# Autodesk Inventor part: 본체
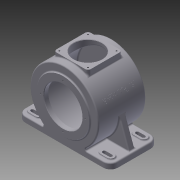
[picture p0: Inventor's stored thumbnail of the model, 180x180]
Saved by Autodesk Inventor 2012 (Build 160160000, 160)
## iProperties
Created: 2015-06
Part Number: 본체
Material: 알루미늄-6061
Document SubType Name: Modeling
Designer: Administrator
Density: 2.71 g/cm^3
Mass: 3341.53 g
Surface Area: 2292.88 cm^2
Volume: 1233.04 cm^3
Author: Administrator
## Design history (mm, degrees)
node "작업 평면2"
sketch "스케치9"
  geometry: L1 (-72, 0)-(62, 0); L2 (0, 0)-(0, 98.803); L3 (-72, 0)-(-72, 65); L4 (-72, 65)-(-59, 65); L5 (-59, 65)-(-59, 85); L6 (-59, 85)-(59, 85); L7 (59, 85)-(59, 65); L8 (59, 65)-(62, 65); L9 (62, 65)-(62, 0)
  constraints: 18 end point, 4 parallel, 4 perpendicular, 1 horizontal
  dimensions: "d23" = 72 distance from line of L2 L1.start; "d24" = 134 distance of L1.start L1.end; "d25" = 0 distance from line of L1 L2.start; "d26" = 13 distance of L3.end L4.end; "d27" = 118 distance of L5.end L6.end; "d28" = 130 diameter of L4 L1; "d29" = 170 diameter of L6 L1; "d30" = 130 diameter of L8 L1
revolve "회전2" sketch "스케치9" stored, may be unused: angle "d31" = 90 deg
sketch "스케치10"
  geometry: L1 (-115, 59)-(115, 59); L2 (115, 59)-(115, -59); L3 (115, -59)-(-115, -59); L4 (-115, -59)-(-115, 59); 2 further points
  constraints: 8 end point, 2 parallel, 1 horizontal, 1 midpoint, 1 perpendicular, 1 vertical alignment
  dimensions: "d32" = 118 distance of L3.end L1.start; "d34" = 230 distance of L1.start L1.end; "d37" = 59 distance from line of L3 point (0, 0)
extrude "돌출4" join sketch "스케치10" distance "d35" = 14; taper "d36" = 0 deg
sketch "스케치12"
  geometry: L1 (-115, -71)-(-46.733, -71) reference; L2 (46.733, -71)-(115, -71) reference; L3 (115, -85)-(115, -71) reference; L4 (-115, -85)-(115, -85) reference; L5 (-115, -85)-(-115, -71) reference; L6 (-115, -71)-(-46.733, -71) reference; L7 (-109, -71)-(-84.87, -4.703); C1 r 65 at (0, 0) reference; A1 r 85 centre (0, 0) between (46.733, -71) and (-46.733, -71) reference; A2 r 85 centre (0, 0) between (46.733, -71) and (-46.733, -71) reference; 1 further point
  constraints: 2 end point, 1 point on circle, 1 point on line
  dimensions: "d38" = 110 deg angle of L7 L1; "d39" = 6 distance from line of L7.start L5
extrude "돌출5" join sketch "스케치12" stored distance "d40" = 15; taper "d41" = 0 deg
node "작업 평면3"
sketch "스케치13"
  geometry: L1 (-42.5, 42.5)-(42.5, 42.5); L2 (42.5, 42.5)-(42.5, -42.5); L3 (42.5, -42.5)-(-42.5, -42.5); L4 (-42.5, -42.5)-(-42.5, 42.5); 3 further points
  constraints: 8 end point, 2 midpoint, 2 parallel, 1 horizontal, 1 horizontal alignment, 1 perpendicular, 1 vertical alignment
  dimensions: "d43" = 85 distance of L1.start L1.end; "d44" = 85 distance of L3.end L1.start
extrude "돌출6" join sketch "스케치13" stored distance "d45" = 15; taper "d46" = 0 deg
sketch "스케치14"
  geometry: L1 (-72, -65)-(-72, 65) reference; L2 (62, -65)-(62, 65) reference; L3 (-42.5, 88)-(42.5, 88) reference; L4 (-72, 0)-(62, 0); L5 (-64.5, 0)-(-64.5, 12); L6 (-61.5, 15)-(-61.5, 15); L7 (-61.5, 15)-(-61.5, 23.2); L8 (-61.2, 23.5)-(-48.5, 23.5); L9 (-47.5, 24.5)-(-47.5, 29.368); L10 (-47.5, 29.368)-(-49.268, 30.192); L11 (-51, 32.911)-(-51, 74); L12 (-48, 77)-(48, 77); L13 (51, 74)-(51, 47.5); L14 (51, 47.5)-(62, 47.5); L15 (-48.5, 23.5)-(-47.5, 24.5); L16 (59, -71)-(59, 85) reference; A1 r 0.3 centre (-61.2, 23.2) between (-61.2, 23.5) and (-61.5, 23.2); A2 r 3 centre (-61.5, 12) between (-61.5, 15) and (-64.5, 12); A3 r 3 centre (-48, 74) between (-48, 77) and (-51, 74); A4 r 3 centre (48, 74) between (51, 74) and (48, 77); A5 r 3 centre (-48, 32.911) between (-51, 32.911) and (-49.268, 30.192); 7 further points
  constraints: 24 end point, 14 point on line, 10 point on circle, 10 tangent, 6 parallel, 5 centre point, 3 perpendicular, 2 equal radius, 2 midpoint
  dimensions: "d47" = 154 diameter of L12 L4; "d48" = 102 distance of point (-51, 77) point (51, 77); "d50" = 95 diameter of L14 L4; "d51" = 115 deg angle of L11 L10; "d52" = 62 diameter of point (-51, 31) L4; "d53" = 14 distance of point (-61.5, 23.5) point (-47.5, 23.5); "d54" = 3 distance of point (-64.5, 15) L6.end; "d55" = 47 diameter of L8 L4; "d56" = 30 diameter of L6 L4; "d57" = 3.5 distance between parallel lines of L11 L9; "d58" = 0.3 radius of A1; "d59" = 3 radius of A2; "d60" = 1 distance of L8.end point (-47.5, 23.5); "d61" = 1 distance of L9.start point (-47.5, 23.5) (= d60); "d62" = 3 radius of A3; "d129" = 8 distance between parallel lines of L16 L13
revolve "회전3" sketch "스케치14" stored, may be unused: angle "d63" = 90 deg
chamfer "모따기1" distance "d64" = 1; stored, may be unused: second distance "d65" = 2, angle "d66" = 45 deg
sketch "스케치15"
  geometry: C1 r 35 at (0, 0); 1 further point
  constraints: 1 centre point, 1 coincident
  dimensions: "d67" = 70 diameter of C1
extrude "돌출7" cut sketch "스케치15" distance "d68" = 50; taper "d69" = 0 deg
fillet "모깎기1" dims "d70" = 3
chamfer "모따기2" distance "d71" = 1; stored, may be unused: second distance "d72" = 2, angle "d73" = 45 deg
sketch "스케치16"
  geometry: C1 r 36 at (0, 0) reference; 4 further points
  constraints: 2 horizontal alignment, 2 vertical alignment
  dimensions: "d74" = 71 distance of point (-35.5, -35.5) point (-35.5, 35.5); "d75" = 35.5 horizontal distance of C1.centre point (-35.5, 35.5); "d76" = 71 distance of point (35.5, 35.5) point (-35.5, 35.5) (= d74); "d77" = 35.5 horizontal distance of point (-35.5, 35.5) C1.centre (= d75)
hole "구멍1" sketch "스케치16" at (-35.5, 35.5), (-35.5, -35.5), (35.5, 35.5), (35.5, -35.5) diameter "d78" = 3.242; stored, may be unused: countersink angle "d82" = 90 deg, drill point angle "d84" = 118 deg; dims "d79" = 10, "d80" = 4, "d81" = 2, "d83" = 13
sketch "스케치17"
  geometry: L1 (115, -59)-(46.733, -59) reference; L2 (115, 59)-(115, -59) reference; L3 (97, -45)-(81, -45); L4 (97, -37)-(81, -37); A1 r 4 centre (97, -41) between (97, -45) and (97, -37); A2 r 4 centre (81, -41) between (81, -37) and (81, -45); 1 further point
  constraints: 4 end point, 4 point on circle, 4 tangent, 2 centre point, 1 horizontal alignment
  dimensions: "d85" = 8 diameter of A1; "d86" = 8 diameter of A2; "d87" = 16 distance of A2.centre A1.centre; "d88" = 18 distance from line of A1.centre L2; "d89" = 18 distance from line of A1.centre L1
extrude "돌출8" cut sketch "스케치17" distance "d90" = 50; taper "d91" = 0 deg
sketch "스케치18"
  geometry: L1 (81, -37)-(97, -37) reference; L2 (97, -45)-(81, -45) reference; L3 (81, -32)-(97, -32); L4 (81, -50)-(97, -50); A1 r 4 centre (97, -41) between (97, -45) and (97, -37) reference; A2 r 4 centre (81, -41) between (81, -37) and (81, -45) reference; A3 r 9 centre (97, -41) between (88.938, -45) and (89, -45.123); A4 r 9 centre (81, -41) between (89, -45.123) and (89.062, -45); A5 r 9 centre (97, -41) between (97, -50) and (97, -32); A6 r 9 centre (97, -41) between (89, -36.877) and (88.938, -37); A7 r 9 centre (81, -41) between (89.062, -37) and (89, -36.877); A8 r 9 centre (81, -41) between (81, -32) and (81, -50); 1 further point
  constraints: 12 point on circle, 6 centre point, 4 end point, 4 point on line, 3 tangent, 2 coincident, 1 parallel
  dimensions: "d94" = 9 radius of A8; "d95" = 9 radius of A5 (= d94)
extrude "돌출9" join sketch "스케치18" distance "d96" = 3; taper "d97" = 0 deg
fillet "모깎기2" dims "d98" = 3
fillet "모깎기3" dims "d105" = 18
sketch "스케치19"
  geometry: C1 r 65 at (0, 0) reference; 1 further point
  constraints: 1 vertical alignment
  dimensions: "d106" = 55 distance of C1.centre point (0, 55)
hole "구멍2" sketch "스케치19" at (0, 55) diameter "d107" = 3.242; stored, may be unused: countersink angle "d111" = 90 deg, drill point angle "d113" = 118 deg; dims "d108" = 10, "d109" = 4, "d110" = 2, "d112" = 13
fillet "모깎기4" dims "d117" = 3
fillet "모깎기5" dims "d118" = 7
fillet "모깎기6" dims "d119" = 3
node "작업 평면8"
  node "작업 평면6"
sketch "스케치22"
  geometry: 2 further points
  constraints: 1 coincident, 1 other
  dimensions: "d126" = 0 distance of point (0, 0) point (0, 0)
feature "엠보싱1" sketch "스케치22" dims "d23" = 72, "d24" = 134, "d25" = 0, "d26" = 13, "d27" = 118, "d28" = 130, "d29" = 170, "d30" = 130, "d127" = 0.5, "d128" = 0
node "솔리드3"
mirror "대칭1"
pattern_linear "직사각형 패턴1" dims "d101" = 178, "d104" = 82
pattern_circular "원형 패턴1" dims angle "d115" = 360 deg
node "투영된 루프2"
other parameters: "d17" = -85, "d42" = 173, "d92" = 18, "d93" = 18, "d122" = 295 deg, "d125" = 85
